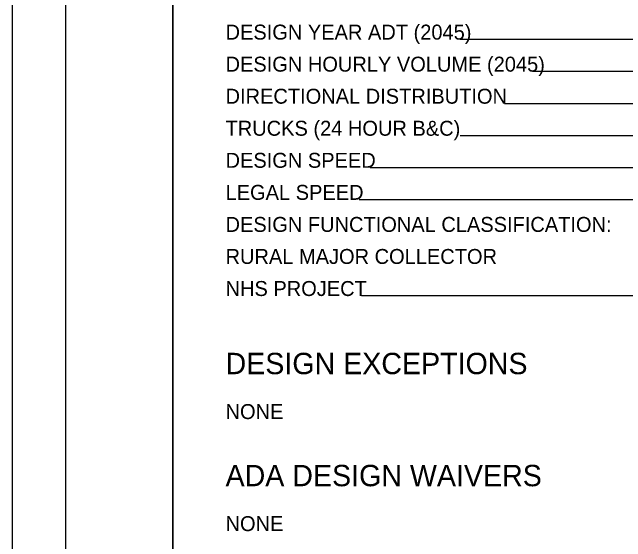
# Model space of a CAD drawing. Extents: x -4 to 116, y -17 to 29.
# Drawn here: x 48.48 to 54.22, y -9.8 to -4.84 of the extents above; entities that cross this region are included whole.
import ezdxf

# ---------------------------------------------------------------- set-up
doc = ezdxf.new("R2010")
doc.units = 0
for name, color, linetype in [('SH_Border', 7, 'Continuous'), ('SH_Cut_Line', 7, 'Continuous'), ('SH_Data', 7, 'Continuous'), ('SH_Text', 7, 'Continuous')]:
    doc.layers.add(name, color=color, linetype=linetype)

msp = doc.modelspace()

# ---------------------------------------------------------------- linework, layer by layer
at = {"layer": 'SH_Border'}
for points in [[(48.9833, 6.8947), (49.9833, 6.8947), (49.9833, -14.1053), (48.9833, -14.1053)], [(49.9833, 6.8947), (81.9833, 6.8947), (81.9833, -14.1053), (49.9833, -14.1053)]]:
    msp.add_lwpolyline(points, close=True, dxfattribs=at)
at = {"layer": 'SH_Cut_Line'}
msp.add_lwpolyline([(48.4833, -14.6053), (82.4833, -14.6053), (82.4833, 7.3947), (48.4833, 7.3947)], close=True, dxfattribs=at)
at = {"layer": 'SH_Data'}
for p, q in [((56.1201, -5.0991), (52.6718, -5.0991)), ((56.1201, -5.3991), (53.3556, -5.3991)), ((56.1201, -5.6991), (53.087, -5.6991)), ((56.1201, -5.9991), (52.6718, -5.9991)), ((56.1201, -6.2991), (51.8292, -6.2991)), ((56.1201, -6.5991), (51.7255, -6.5991)), ((56.1201, -7.4991), (51.7502, -7.4991))]:
    msp.add_line(p, q, dxfattribs=at)

# ---------------------------------------------------------------- texts
at = {"layer": 'SH_Text'}
for s, height, p in [('DESIGN YEAR ADT (2045)', 0.14, (50.4777, -5.0991)), ('DESIGN HOURLY VOLUME (2045)', 0.14, (50.4777, -5.3991)), ('DIRECTIONAL DISTRIBUTION', 0.14, (50.4777, -5.6991)), ('TRUCKS (24 HOUR B&C)', 0.14, (50.4777, -5.9991)), ('DESIGN SPEED', 0.14, (50.4777, -6.2991)), ('LEGAL SPEED', 0.14, (50.4777, -6.5991)), ('DESIGN FUNCTIONAL CLASSIFICATION:', 0.14, (50.4777, -6.8991)), ('RURAL MAJOR COLLECTOR', 0.14, (50.4777, -7.1991)), ('NHS PROJECT', 0.14, (50.4777, -7.4991)), ('DESIGN EXCEPTIONS', 0.2, (50.4777, -8.2309)), ('NONE', 0.14, (50.4777, -8.6509)), ('ADA DESIGN WAIVERS', 0.2, (50.4777, -9.2797)), ('NONE', 0.14, (50.4777, -9.6997))]:
    msp.add_text(s, height=height, dxfattribs=at).set_placement(p)

doc.saveas('drawing.dxf')
